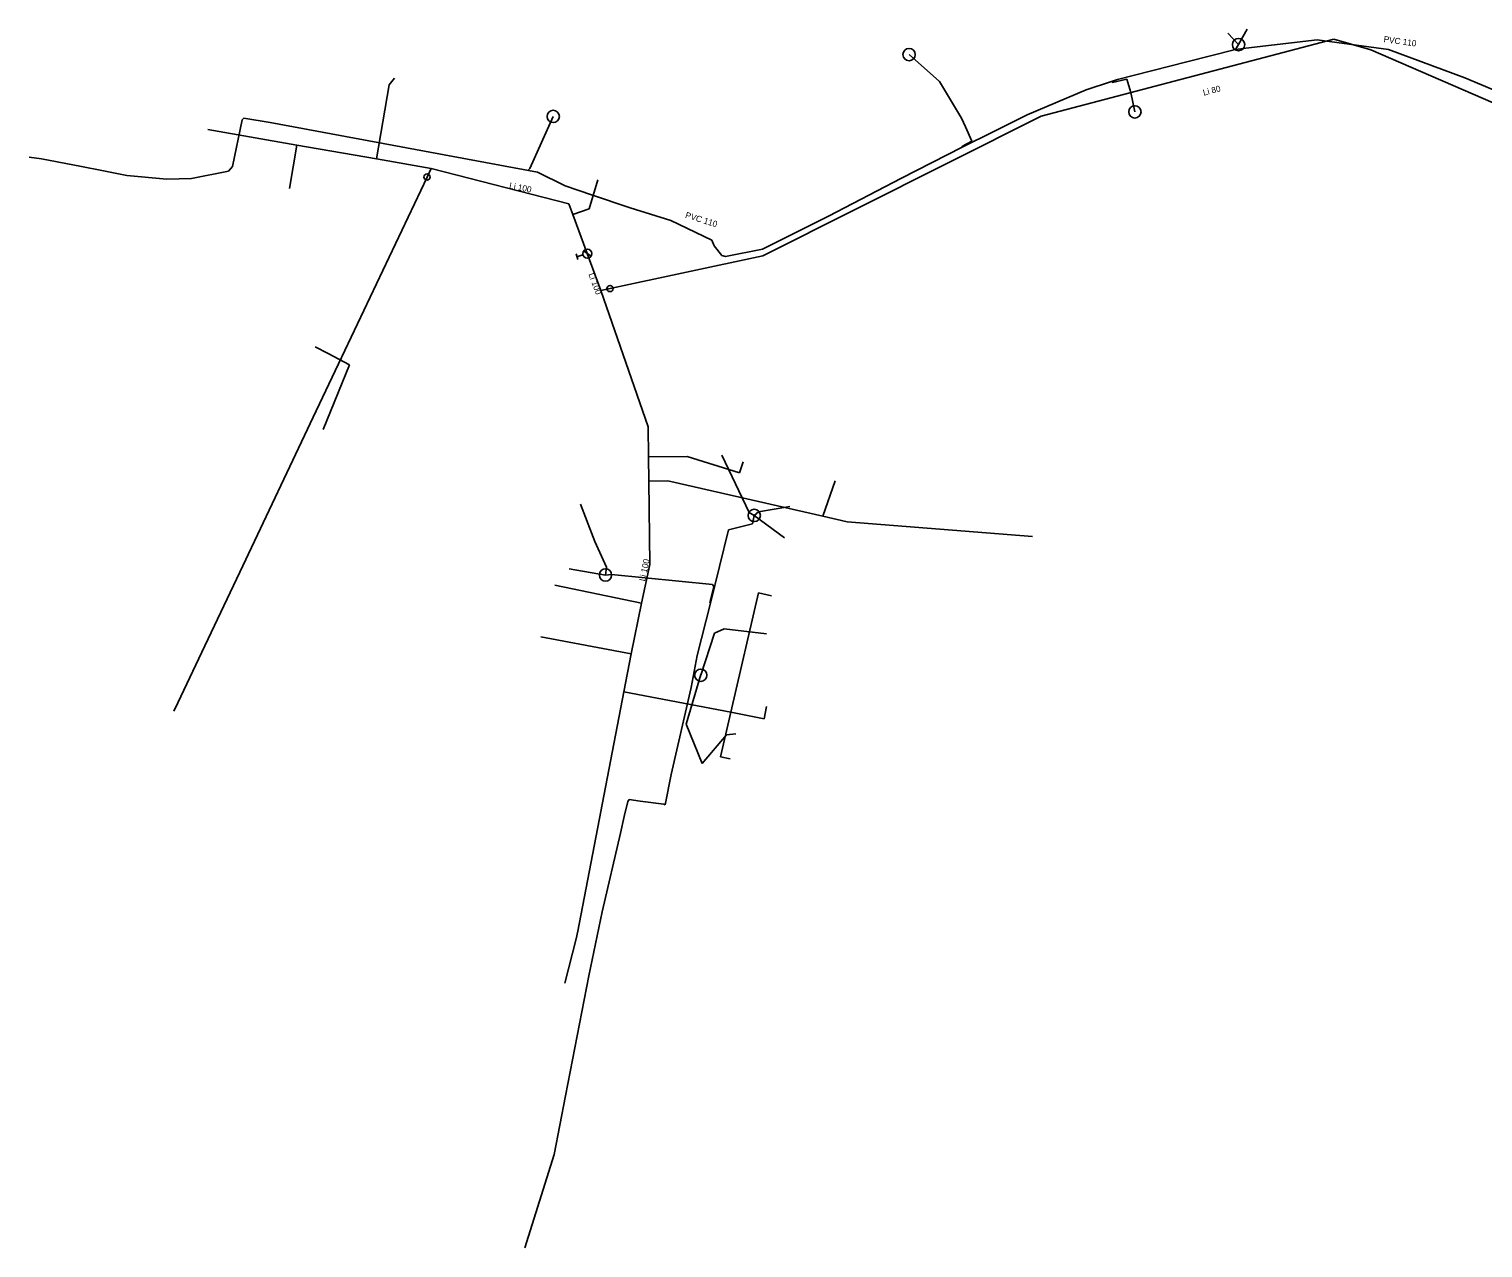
# Model space of a CAD drawing. Extents: x -686883 to -686397, y -1053920 to -1053689.
# Drawn here: x -686882.6 to -686646.7, y -1053919.8 to -1053721.9 of the extents above; entities that cross this region are included whole.
import ezdxf

# ---------------------------------------------------------------- set-up
doc = ezdxf.new("R2010")
doc.units = 0
doc.layers.add('Level 0', color=7, linetype='Continuous')

msp = doc.modelspace()

# ---------------------------------------------------------------- linework, layer by layer
at = {"layer": 'Level 0'}
for p, q in [((-686718.37, -1053736.02), (-686670.85, -1053723.49)), ((-686686.33, -1053724.39), (-686688.04, -1053722.54)), ((-686686.33, -1053724.39), (-686684.94, -1053721.86)), ((-686673.54, -1053723.61), (-686685.12, -1053724.97)), ((-686661.97, -1053725.17), (-686673.54, -1053723.61)), ((-686670.85, -1053723.49), (-686664.83, -1053725.24)), ((-686670.85, -1053723.49), (-686664.83, -1053725.24)), ((-686734.87, -1053730.38), (-686739.81, -1053726.01)), ((-686686.82, -1053725.17), (-686694.7, -1053727.16)), ((-686686.82, -1053725.17), (-686686.33, -1053724.39)), ((-686685.12, -1053724.97), (-686686.82, -1053725.17)), ((-686664.83, -1053725.24), (-686641.74, -1053735.22)), ((-686649.61, -1053729.79), (-686661.97, -1053725.17)), ((-686694.7, -1053727.16), (-686705.98, -1053730.07)), ((-686824.17, -1053730.94), (-686823.35, -1053729.81)), ((-686731.31, -1053736.35), (-686734.87, -1053730.38)), ((-686706.94, -1053730.37), (-686711.05, -1053731.74)), ((-686705.98, -1053730.07), (-686706.94, -1053730.37)), ((-686706.94, -1053730.37), (-686706.8, -1053730.52)), ((-686706.8, -1053730.52), (-686704.48, -1053730.02)), ((-686704.48, -1053730.02), (-686703.82, -1053732.14)), ((-686642.52, -1053732.76), (-686649.61, -1053729.79)), ((-686826.27, -1053742.94), (-686824.17, -1053730.94)), ((-686711.05, -1053731.74), (-686720.63, -1053735.79)), ((-686703.82, -1053732.14), (-686703.16, -1053735.31)), ((-686848.03, -1053736.6), (-686849.61, -1053744.15)), ((-686847.77, -1053736.35), (-686848.03, -1053736.6)), ((-686843.5, -1053737.05), (-686847.77, -1053736.35)), ((-686800.14, -1053745.09), (-686843.5, -1053737.05)), ((-686801.37, -1053744.49), (-686797.57, -1053736.04)), ((-686763.54, -1053758.68), (-686718.37, -1053736.02)), ((-686730.67, -1053737.74), (-686731.31, -1053736.35)), ((-686729.63, -1053740.04), (-686730.67, -1053737.74)), ((-686720.63, -1053735.79), (-686726.07, -1053738.51)), ((-686839.16, -1053740.69), (-686853.63, -1053738.17)), ((-686726.07, -1053738.51), (-686731.19, -1053741.05)), ((-686731.11, -1053740.88), (-686729.63, -1053740.04)), ((-686839.16, -1053740.69), (-686840.39, -1053747.73)), ((-686826.27, -1053742.94), (-686839.16, -1053740.69)), ((-686731.19, -1053741.05), (-686741.03, -1053746.06)), ((-686731.19, -1053741.05), (-686731.11, -1053740.88)), ((-686880.65, -1053742.95), (-686882.64, -1053742.68)), ((-686874.11, -1053744.16), (-686880.65, -1053742.95)), ((-686870.82, -1053744.8), (-686874.11, -1053744.16)), ((-686866.76, -1053745.65), (-686870.82, -1053744.8)), ((-686850.29, -1053744.95), (-686856.25, -1053746.12)), ((-686849.61, -1053744.15), (-686850.29, -1053744.95)), ((-686817.39, -1053744.49), (-686826.27, -1053742.94)), ((-686817.39, -1053744.49), (-686818.05, -1053745.89)), ((-686795.02, -1053750.21), (-686817.39, -1053744.49)), ((-686801.69, -1053744.8), (-686801.37, -1053744.49)), ((-686860.26, -1053746.23), (-686866.76, -1053745.65)), ((-686856.25, -1053746.12), (-686860.26, -1053746.23)), ((-686818.05, -1053745.89), (-686832.43, -1053776.23)), ((-686795.64, -1053747.34), (-686800.14, -1053745.09)), ((-686791.75, -1053751.03), (-686790.3, -1053746.33)), ((-686741.03, -1053746.06), (-686752.9, -1053752.26)), ((-686791.33, -1053748.8), (-686795.64, -1053747.34)), ((-686785.08, -1053750.88), (-686791.33, -1053748.8)), ((-686794.36, -1053751.99), (-686795.02, -1053750.21)), ((-686794.36, -1053751.99), (-686791.75, -1053751.03)), ((-686792.03, -1053758.32), (-686794.36, -1053751.99)), ((-686778.48, -1053752.92), (-686785.08, -1053750.88)), ((-686771.81, -1053756.13), (-686778.48, -1053752.92)), ((-686752.9, -1053752.26), (-686763.61, -1053757.59)), ((-686771.45, -1053757.06), (-686771.81, -1053756.13)), ((-686793.56, -1053759.3), (-686793.85, -1053758.34)), ((-686792.75, -1053758.54), (-686793.71, -1053758.82)), ((-686791.42, -1053758.75), (-686792.64, -1053757.89)), ((-686789.82, -1053764.31), (-686792.03, -1053758.32)), ((-686788.34, -1053763.99), (-686763.54, -1053758.68)), ((-686770.18, -1053758.62), (-686771.45, -1053757.06)), ((-686769.58, -1053758.76), (-686770.18, -1053758.62)), ((-686763.61, -1053757.59), (-686769.58, -1053758.76)), ((-686789.82, -1053764.31), (-686788.34, -1053763.99)), ((-686782.17, -1053786.44), (-686789.82, -1053764.31)), ((-686836.22, -1053773.43), (-686834.09, -1053774.52)), ((-686834.09, -1053774.52), (-686830.64, -1053776.35)), ((-686832.43, -1053776.23), (-686836.03, -1053783.83)), ((-686830.64, -1053776.35), (-686834.92, -1053786.86)), ((-686836.03, -1053783.83), (-686848.45, -1053810.05)), ((-686782.11, -1053791.31), (-686782.17, -1053786.44)), ((-686782.11, -1053791.31), (-686775.82, -1053791.24)), ((-686782.07, -1053795.24), (-686782.11, -1053791.31)), ((-686775.82, -1053791.24), (-686767.33, -1053793.93)), ((-686770.22, -1053791.06), (-686770.22, -1053791.05)), ((-686765.75, -1053800.34), (-686770.22, -1053791.06)), ((-686767.33, -1053793.93), (-686766.76, -1053792.12)), ((-686782.07, -1053795.24), (-686778.98, -1053795.2)), ((-686781.91, -1053808.82), (-686782.07, -1053795.24)), ((-686778.98, -1053795.2), (-686753.81, -1053800.95)), ((-686751.81, -1053795.2), (-686753.81, -1053800.95)), ((-686793.13, -1053799.02), (-686793.16, -1053799.02)), ((-686790.82, -1053805.06), (-686793.13, -1053799.02)), ((-686764.93, -1053800.83), (-686765.75, -1053800.34)), ((-686765.22, -1053802.17), (-686764.93, -1053800.83)), ((-686764.93, -1053800.83), (-686764.24, -1053800.24)), ((-686764.93, -1053800.83), (-686760.02, -1053804.47)), ((-686764.24, -1053800.24), (-686759.18, -1053799.39)), ((-686753.81, -1053800.95), (-686749.84, -1053801.86)), ((-686772.01, -1053815.08), (-686769.13, -1053803.16)), ((-686769.13, -1053803.16), (-686765.22, -1053802.17)), ((-686749.84, -1053801.86), (-686719.75, -1053804.24)), ((-686788.94, -1053809.23), (-686790.82, -1053805.06)), ((-686848.45, -1053810.05), (-686854.12, -1053822.01)), ((-686789.08, -1053810.5), (-686795, -1053809.49)), ((-686789.08, -1053810.5), (-686788.94, -1053809.23)), ((-686788.12, -1053810.4), (-686789.08, -1053810.5)), ((-686771.69, -1053812.04), (-686788.12, -1053810.4)), ((-686783.22, -1053815.09), (-686781.91, -1053808.82)), ((-686783.22, -1053815.09), (-686797.32, -1053812.14)), ((-686772.15, -1053814.97), (-686771.47, -1053812.36)), ((-686771.47, -1053812.36), (-686771.69, -1053812.04)), ((-686764.25, -1053813.38), (-686768.75, -1053832.79)), ((-686762.15, -1053813.87), (-686764.25, -1053813.38)), ((-686784.94, -1053823.28), (-686783.22, -1053815.09)), ((-686774.18, -1053823.56), (-686772.01, -1053815.08)), ((-686772.01, -1053815.08), (-686772.15, -1053814.97)), ((-686773.62, -1053826.77), (-686771.38, -1053819.95)), ((-686771.38, -1053819.95), (-686769.84, -1053819.22)), ((-686769.84, -1053819.22), (-686762.92, -1053820.07)), ((-686854.12, -1053822.01), (-686858.49, -1053831.25)), ((-686784.94, -1053823.28), (-686799.58, -1053820.54)), ((-686786.12, -1053829.45), (-686784.94, -1053823.28)), ((-686775.19, -1053828.79), (-686774.18, -1053823.56)), ((-686776, -1053834.7), (-686773.59, -1053826.67)), ((-686793.59, -1053868.31), (-686786.12, -1053829.45)), ((-686786.12, -1053829.45), (-686768.75, -1053832.79)), ((-686778.43, -1053842.9), (-686775.19, -1053828.79)), ((-686858.49, -1053831.25), (-686859.15, -1053832.63)), ((-686763.3, -1053833.83), (-686762.92, -1053831.84)), ((-686768.75, -1053832.79), (-686770.43, -1053840.01)), ((-686768.75, -1053832.79), (-686763.3, -1053833.83)), ((-686773.39, -1053841.11), (-686776, -1053834.7)), ((-686773.39, -1053841.11), (-686769.44, -1053836.43)), ((-686769.44, -1053836.43), (-686767.91, -1053836.29)), ((-686770.43, -1053840.01), (-686768.87, -1053840.37)), ((-686779.39, -1053847.79), (-686778.43, -1053842.9)), ((-686786.03, -1053849.69), (-686785.48, -1053847.26)), ((-686785.48, -1053847.26), (-686785.26, -1053846.94)), ((-686785.26, -1053846.94), (-686783.44, -1053847.22)), ((-686783.44, -1053847.22), (-686779.61, -1053847.72)), ((-686779.61, -1053847.72), (-686779.39, -1053847.79)), ((-686786.67, -1053852.4), (-686786.03, -1053849.69)), ((-686789.64, -1053865.18), (-686786.67, -1053852.4)), ((-686791.8, -1053875.57), (-686789.64, -1053865.18)), ((-686795.66, -1053876.78), (-686793.83, -1053869.56)), ((-686793.83, -1053869.56), (-686793.59, -1053868.31)), ((-686795.56, -1053895.04), (-686791.8, -1053875.57)), ((-686797.39, -1053904.58), (-686795.56, -1053895.04)), ((-686802.15, -1053919.76), (-686797.39, -1053904.58))]:
    msp.add_line(p, q, dxfattribs=at)
for centre, radius in [((-686686.33, -1053724.39), 1), ((-686739.81, -1053726.01), 1), ((-686797.57, -1053736.04), 1), ((-686703.16, -1053735.31), 1), ((-686818.05, -1053745.89), 0.5), ((-686792.03, -1053758.32), 0.75), ((-686788.34, -1053763.99), 0.5), ((-686764.93, -1053800.83), 1), ((-686789.08, -1053810.5), 1), ((-686773.62, -1053826.77), 1)]:
    msp.add_circle(centre, radius, dxfattribs=at)

# ---------------------------------------------------------------- texts
for s, rotation, p in [('PVC 110', 352.321, (-686662.83, -1053723.98)), ('Li 80', 14.771, (-686691.96, -1053732.69)), ('Li 100', 348.604, (-686804.77, -1053747.72)), ('PVC 110', 342.824, (-686776.22, -1053752.48)), ('Li 100', 290.251, (-686791.86, -1053761.66)), ('Li 100', 78.199, (-686782.66, -1053811.58))]:
    msp.add_text(s, height=1, rotation=rotation, dxfattribs=at).set_placement(p)

doc.saveas('drawing.dxf')
